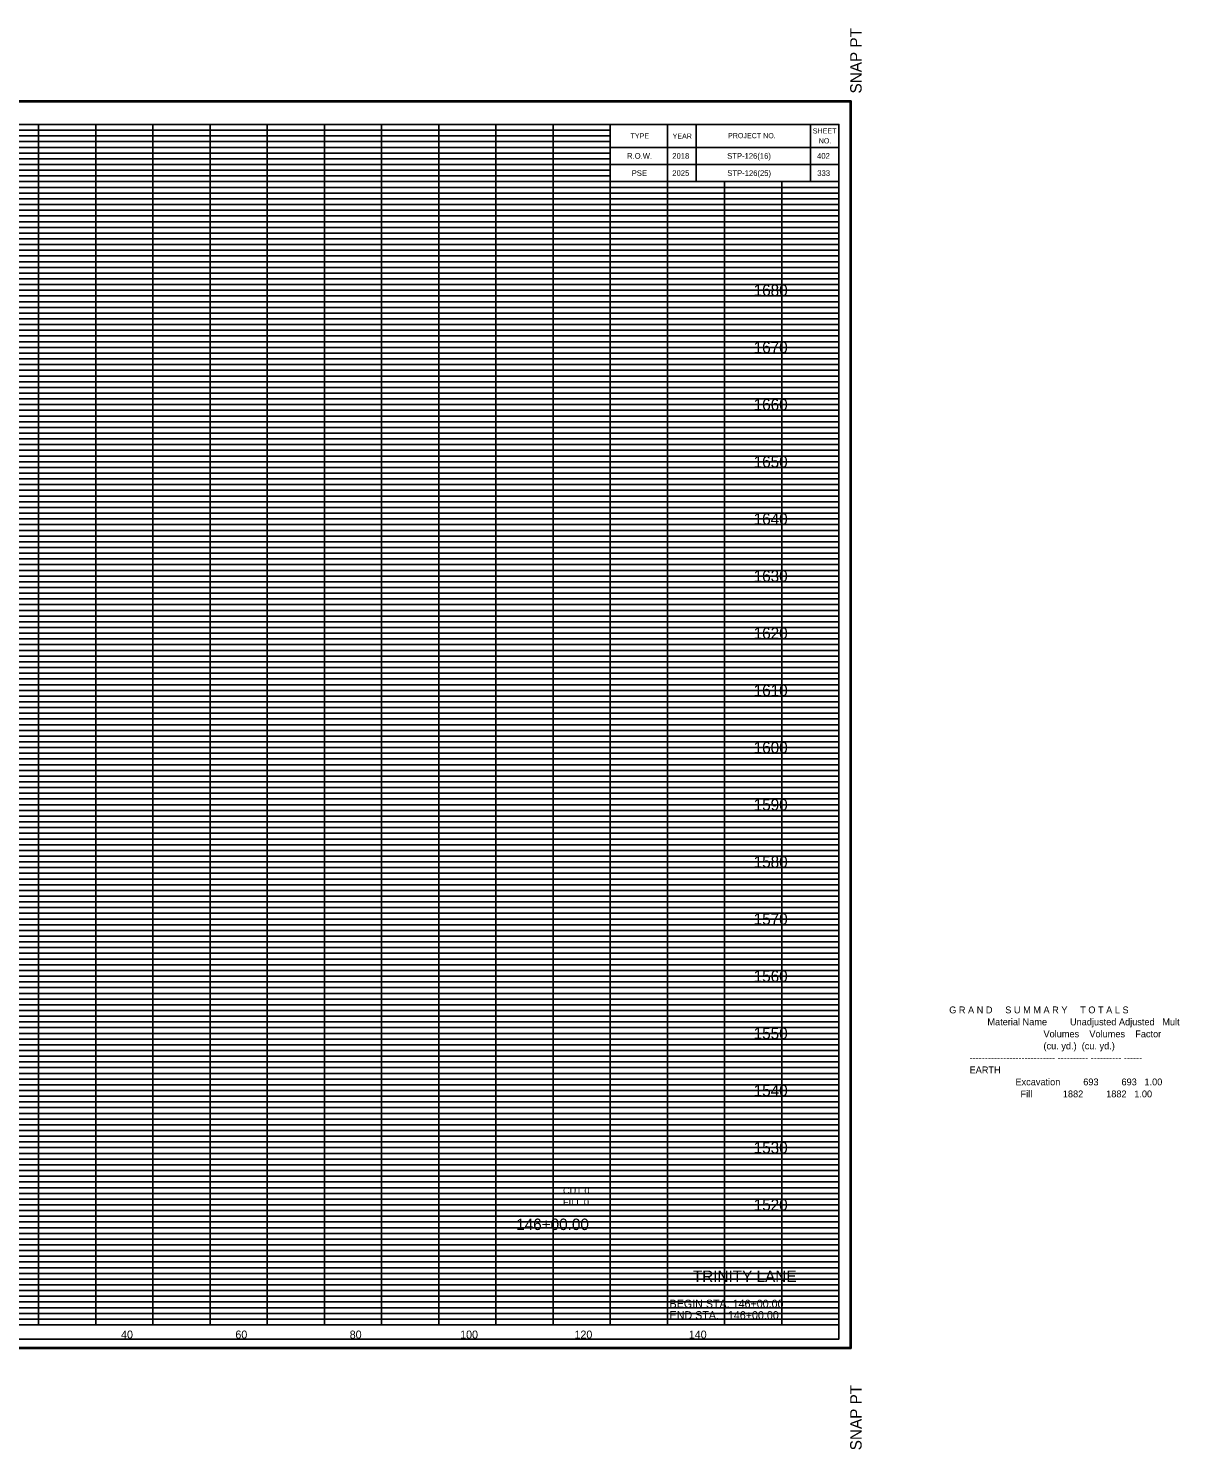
# Model space of a CAD drawing. Extents: x 980 to 1380, y 1248 to 3387.
# Drawn here: x 1178.2 to 1379.6, y 1248.2 to 1496.8 of the extents above; entities that cross this region are included whole.
import ezdxf

# ---------------------------------------------------------------- set-up
doc = ezdxf.new("R2010")
doc.units = 0
for name, color, linetype in [('DESIGN - SCRATCH - User 1', 7, 'Continuous'), ('DESIGN - SHEET - Corner Text', 7, 'Continuous'), ('DESIGN - SHEET - Light Grid', 7, 'Continuous'), ('DESIGN - SHEET - Linework', 7, 'Continuous'), ('DESIGN - SHEET - Plot Shape', 7, 'Continuous'), ('DESIGN - TYPICAL - Text', 7, 'Continuous')]:
    doc.layers.add(name, color=color, linetype=linetype)

# ---------------------------------------------------------------- blocks, each defined once
blk = doc.blocks.new('XSTSHT')
at = {"layer": 'DESIGN - SCRATCH - User 1'}
for p, q in [((28.5, 20.45), (28.5, 20.45)), ((29.24, 20.45), (29.24, 20.45)), ((30.49, 20.45), (30.49, 20.45)), ((31.74, 20.45), (31.74, 20.45)), ((28.5, 20.15), (28.5, 20.15)), ((29.24, 20.15), (29.24, 20.15)), ((30.49, 20.15), (30.49, 20.15)), ((31.74, 20.15), (31.74, 20.15))]:
    blk.add_line(p, q, dxfattribs=at)
at = {"layer": 'DESIGN - SHEET - Light Grid'}
for p, q in [((16, 20.9), (24, 20.9)), ((24, 20.9), (28, 20.9)), ((16, 20.8), (24, 20.8)), ((16, 20.7), (24, 20.7)), ((24, 20.8), (28, 20.8)), ((24, 20.7), (28, 20.7)), ((16, 20.6), (24, 20.6)), ((16, 20.5), (24, 20.5)), ((16, 20.4), (24, 20.4)), ((24, 20.6), (28, 20.6)), ((24, 20.5), (28, 20.5)), ((24, 20.4), (28, 20.4)), ((16, 20.3), (24, 20.3)), ((16, 20.2), (24, 20.2)), ((24, 20.3), (28, 20.3)), ((24, 20.2), (28, 20.2)), ((16, 20.1), (24, 20.1)), ((16, 19.9), (24, 19.9)), ((24, 20.1), (28, 20.1)), ((24, 19.9), (32, 19.9)), ((16, 19.8), (24, 19.8)), ((16, 19.7), (24, 19.7)), ((24, 19.8), (32, 19.8)), ((24, 19.7), (32, 19.7)), ((16, 19.6), (24, 19.6)), ((16, 19.5), (24, 19.5)), ((16, 19.4), (24, 19.4)), ((24, 19.6), (32, 19.6)), ((24, 19.5), (32, 19.5)), ((24, 19.4), (32, 19.4)), ((16, 19.3), (24, 19.3)), ((16, 19.2), (24, 19.2)), ((24, 19.3), (32, 19.3)), ((24, 19.2), (32, 19.2)), ((16, 19.1), (24, 19.1)), ((16, 18.9), (24, 18.9)), ((24, 19.1), (32, 19.1)), ((24, 18.9), (32, 18.9)), ((16, 18.8), (24, 18.8)), ((16, 18.7), (24, 18.7)), ((24, 18.8), (32, 18.8)), ((24, 18.7), (32, 18.7)), ((16, 18.6), (24, 18.6)), ((16, 18.5), (24, 18.5)), ((16, 18.4), (24, 18.4)), ((24, 18.6), (32, 18.6)), ((24, 18.5), (32, 18.5)), ((24, 18.4), (32, 18.4)), ((16, 18.3), (24, 18.3)), ((16, 18.2), (24, 18.2)), ((24, 18.3), (32, 18.3)), ((24, 18.2), (32, 18.2)), ((16, 18.1), (24, 18.1)), ((24, 18.1), (32, 18.1)), ((16, 17.9), (24, 17.9)), ((16, 17.8), (24, 17.8)), ((16, 17.7), (24, 17.7)), ((24, 17.9), (32, 17.9)), ((24, 17.8), (32, 17.8)), ((24, 17.7), (32, 17.7)), ((16, 17.6), (24, 17.6)), ((16, 17.5), (24, 17.5)), ((24, 17.6), (32, 17.6)), ((24, 17.5), (32, 17.5)), ((16, 17.4), (24, 17.4)), ((16, 17.3), (24, 17.3)), ((16, 17.2), (24, 17.2)), ((24, 17.4), (32, 17.4)), ((24, 17.3), (32, 17.3)), ((24, 17.2), (32, 17.2)), ((16, 17.1), (24, 17.1)), ((24, 17.1), (32, 17.1)), ((16, 16.9), (24, 16.9)), ((16, 16.8), (24, 16.8)), ((16, 16.7), (24, 16.7)), ((24, 16.9), (32, 16.9)), ((24, 16.8), (32, 16.8)), ((24, 16.7), (32, 16.7)), ((16, 16.6), (24, 16.6)), ((16, 16.5), (24, 16.5)), ((24, 16.6), (32, 16.6)), ((24, 16.5), (32, 16.5)), ((16, 16.4), (24, 16.4)), ((16, 16.3), (24, 16.3)), ((16, 16.2), (24, 16.2)), ((24, 16.4), (32, 16.4)), ((24, 16.3), (32, 16.3)), ((24, 16.2), (32, 16.2)), ((16, 16.1), (24, 16.1)), ((24, 16.1), (32, 16.1)), ((16, 15.9), (24, 15.9)), ((16, 15.8), (24, 15.8)), ((16, 15.7), (24, 15.7)), ((24, 15.9), (32, 15.9)), ((24, 15.8), (32, 15.8)), ((24, 15.7), (32, 15.7)), ((16, 15.6), (24, 15.6)), ((16, 15.5), (24, 15.5)), ((24, 15.6), (32, 15.6)), ((24, 15.5), (32, 15.5)), ((16, 15.4), (24, 15.4)), ((16, 15.3), (24, 15.3)), ((16, 15.2), (24, 15.2)), ((24, 15.4), (32, 15.4)), ((24, 15.3), (32, 15.3)), ((24, 15.2), (32, 15.2)), ((16, 15.1), (24, 15.1)), ((24, 15.1), (32, 15.1)), ((16, 14.9), (24, 14.9)), ((16, 14.8), (24, 14.8)), ((16, 14.7), (24, 14.7)), ((24, 14.9), (32, 14.9)), ((24, 14.8), (32, 14.8)), ((24, 14.7), (32, 14.7)), ((16, 14.6), (24, 14.6)), ((16, 14.5), (24, 14.5)), ((24, 14.6), (32, 14.6)), ((24, 14.5), (32, 14.5)), ((16, 14.4), (24, 14.4)), ((16, 14.3), (24, 14.3)), ((16, 14.2), (24, 14.2)), ((24, 14.4), (32, 14.4)), ((24, 14.3), (32, 14.3)), ((24, 14.2), (32, 14.2)), ((16, 14.1), (24, 14.1)), ((24, 14.1), (32, 14.1)), ((16, 13.9), (24, 13.9)), ((16, 13.8), (24, 13.8)), ((16, 13.7), (24, 13.7)), ((24, 13.9), (32, 13.9)), ((24, 13.8), (32, 13.8)), ((24, 13.7), (32, 13.7)), ((16, 13.6), (24, 13.6)), ((16, 13.5), (24, 13.5)), ((24, 13.6), (32, 13.6)), ((24, 13.5), (32, 13.5)), ((16, 13.4), (24, 13.4)), ((16, 13.3), (24, 13.3)), ((16, 13.2), (24, 13.2)), ((24, 13.4), (32, 13.4)), ((24, 13.3), (32, 13.3)), ((24, 13.2), (32, 13.2)), ((16, 13.1), (24, 13.1)), ((24, 13.1), (32, 13.1)), ((16, 12.9), (24, 12.9)), ((16, 12.8), (24, 12.8)), ((16, 12.7), (24, 12.7)), ((24, 12.9), (32, 12.9)), ((24, 12.8), (32, 12.8)), ((24, 12.7), (32, 12.7)), ((16, 12.6), (24, 12.6)), ((16, 12.5), (24, 12.5)), ((24, 12.6), (32, 12.6)), ((24, 12.5), (32, 12.5)), ((16, 12.4), (24, 12.4)), ((16, 12.3), (24, 12.3)), ((16, 12.2), (24, 12.2)), ((24, 12.4), (32, 12.4)), ((24, 12.3), (32, 12.3)), ((24, 12.2), (32, 12.2)), ((16, 12.1), (24, 12.1)), ((24, 12.1), (32, 12.1)), ((16, 11.9), (24, 11.9)), ((16, 11.8), (24, 11.8)), ((16, 11.7), (24, 11.7)), ((24, 11.9), (32, 11.9)), ((24, 11.8), (32, 11.8)), ((24, 11.7), (32, 11.7)), ((16, 11.6), (24, 11.6)), ((16, 11.5), (24, 11.5)), ((24, 11.6), (32, 11.6)), ((24, 11.5), (32, 11.5)), ((16, 11.4), (24, 11.4)), ((16, 11.3), (24, 11.3)), ((16, 11.2), (24, 11.2)), ((24, 11.4), (32, 11.4)), ((24, 11.3), (32, 11.3)), ((24, 11.2), (32, 11.2)), ((16, 11.1), (24, 11.1)), ((24, 11.1), (32, 11.1)), ((16, 10.9), (24, 10.9)), ((16, 10.8), (24, 10.8)), ((16, 10.7), (24, 10.7)), ((24, 10.9), (32, 10.9)), ((24, 10.8), (32, 10.8)), ((24, 10.7), (32, 10.7)), ((16, 10.6), (24, 10.6)), ((16, 10.5), (24, 10.5)), ((24, 10.6), (32, 10.6)), ((24, 10.5), (32, 10.5)), ((16, 10.4), (24, 10.4)), ((16, 10.3), (24, 10.3)), ((16, 10.2), (24, 10.2)), ((24, 10.4), (32, 10.4)), ((24, 10.3), (32, 10.3)), ((24, 10.2), (32, 10.2)), ((16, 10.1), (24, 10.1)), ((24, 10.1), (32, 10.1)), ((16, 9.9), (24, 9.9)), ((16, 9.8), (24, 9.8)), ((16, 9.7), (24, 9.7)), ((24, 9.9), (32, 9.9)), ((24, 9.8), (32, 9.8)), ((24, 9.7), (32, 9.7)), ((16, 9.6), (24, 9.6)), ((16, 9.5), (24, 9.5)), ((24, 9.6), (32, 9.6)), ((24, 9.5), (32, 9.5)), ((16, 9.4), (24, 9.4)), ((16, 9.3), (24, 9.3)), ((16, 9.2), (24, 9.2)), ((24, 9.4), (32, 9.4)), ((24, 9.3), (32, 9.3)), ((24, 9.2), (32, 9.2)), ((16, 9.1), (24, 9.1)), ((24, 9.1), (32, 9.1)), ((16, 8.9), (24, 8.9)), ((16, 8.8), (24, 8.8)), ((24, 8.9), (32, 8.9)), ((24, 8.8), (32, 8.8)), ((16, 8.7), (24, 8.7)), ((16, 8.6), (24, 8.6)), ((16, 8.5), (24, 8.5)), ((24, 8.7), (32, 8.7)), ((24, 8.6), (32, 8.6)), ((24, 8.5), (32, 8.5)), ((16, 8.4), (24, 8.4)), ((16, 8.3), (24, 8.3)), ((24, 8.4), (32, 8.4)), ((24, 8.3), (32, 8.3)), ((16, 8.2), (24, 8.2)), ((16, 8.1), (24, 8.1)), ((24, 8.2), (32, 8.2)), ((24, 8.1), (32, 8.1)), ((16, 7.9), (24, 7.9)), ((16, 7.8), (24, 7.8)), ((24, 7.9), (32, 7.9)), ((24, 7.8), (32, 7.8)), ((16, 7.7), (24, 7.7)), ((16, 7.6), (24, 7.6)), ((16, 7.5), (24, 7.5)), ((24, 7.7), (32, 7.7)), ((24, 7.6), (32, 7.6)), ((24, 7.5), (32, 7.5)), ((16, 7.4), (24, 7.4)), ((16, 7.3), (24, 7.3)), ((24, 7.4), (32, 7.4)), ((24, 7.3), (32, 7.3)), ((16, 7.2), (24, 7.2)), ((16, 7.1), (24, 7.1)), ((24, 7.2), (32, 7.2)), ((24, 7.1), (32, 7.1)), ((16, 6.9), (24, 6.9)), ((16, 6.8), (24, 6.8)), ((24, 6.9), (32, 6.9)), ((24, 6.8), (32, 6.8)), ((16, 6.7), (24, 6.7)), ((16, 6.6), (24, 6.6)), ((16, 6.5), (24, 6.5)), ((24, 6.7), (32, 6.7)), ((24, 6.6), (32, 6.6)), ((24, 6.5), (32, 6.5)), ((16, 6.4), (24, 6.4)), ((16, 6.3), (24, 6.3)), ((24, 6.4), (32, 6.4)), ((24, 6.3), (32, 6.3)), ((16, 6.2), (24, 6.2)), ((16, 6.1), (24, 6.1)), ((24, 6.2), (32, 6.2)), ((24, 6.1), (32, 6.1)), ((16, 5.9), (24, 5.9)), ((16, 5.8), (24, 5.8)), ((24, 5.9), (32, 5.9)), ((24, 5.8), (32, 5.8)), ((16, 5.7), (24, 5.7)), ((16, 5.6), (24, 5.6)), ((16, 5.5), (24, 5.5)), ((24, 5.7), (32, 5.7)), ((24, 5.6), (32, 5.6)), ((24, 5.5), (32, 5.5)), ((16, 5.4), (24, 5.4)), ((16, 5.3), (24, 5.3)), ((24, 5.4), (32, 5.4)), ((24, 5.3), (32, 5.3)), ((16, 5.2), (24, 5.2)), ((16, 5.1), (24, 5.1)), ((24, 5.2), (32, 5.2)), ((24, 5.1), (32, 5.1)), ((16, 4.9), (24, 4.9)), ((16, 4.8), (24, 4.8)), ((24, 4.9), (32, 4.9)), ((24, 4.8), (32, 4.8)), ((16, 4.7), (24, 4.7)), ((16, 4.6), (24, 4.6)), ((16, 4.5), (24, 4.5)), ((24, 4.7), (32, 4.7)), ((24, 4.6), (32, 4.6)), ((24, 4.5), (32, 4.5)), ((16, 4.4), (24, 4.4)), ((16, 4.3), (24, 4.3)), ((24, 4.4), (32, 4.4)), ((24, 4.3), (32, 4.3)), ((16, 4.2), (24, 4.2)), ((16, 4.1), (24, 4.1)), ((24, 4.2), (32, 4.2)), ((24, 4.1), (32, 4.1)), ((16, 3.9), (24, 3.9)), ((16, 3.8), (24, 3.8)), ((24, 3.9), (32, 3.9)), ((24, 3.8), (32, 3.8)), ((16, 3.7), (24, 3.7)), ((16, 3.6), (24, 3.6)), ((16, 3.5), (24, 3.5)), ((24, 3.7), (32, 3.7)), ((24, 3.6), (32, 3.6)), ((24, 3.5), (32, 3.5)), ((16, 3.4), (24, 3.4)), ((16, 3.3), (24, 3.3)), ((24, 3.4), (32, 3.4)), ((24, 3.3), (32, 3.3)), ((16, 3.2), (24, 3.2)), ((16, 3.1), (24, 3.1)), ((24, 3.2), (32, 3.2)), ((24, 3.1), (32, 3.1)), ((16, 2.9), (24, 2.9)), ((16, 2.8), (24, 2.8)), ((24, 2.9), (32, 2.9)), ((24, 2.8), (32, 2.8)), ((16, 2.7), (24, 2.7)), ((16, 2.6), (24, 2.6)), ((16, 2.5), (24, 2.5)), ((24, 2.7), (32, 2.7)), ((24, 2.6), (32, 2.6)), ((24, 2.5), (32, 2.5)), ((16, 2.4), (24, 2.4)), ((16, 2.3), (24, 2.3)), ((24, 2.4), (32, 2.4)), ((24, 2.3), (32, 2.3)), ((16, 2.2), (24, 2.2)), ((16, 2.1), (24, 2.1)), ((24, 2.2), (32, 2.2)), ((24, 2.1), (32, 2.1)), ((16, 1.9), (24, 1.9)), ((16, 1.8), (24, 1.8)), ((24, 1.9), (32, 1.9)), ((24, 1.8), (32, 1.8)), ((16, 1.7), (24, 1.7)), ((16, 1.6), (24, 1.6)), ((16, 1.5), (24, 1.5)), ((24, 1.7), (32, 1.7)), ((24, 1.6), (32, 1.6)), ((24, 1.5), (32, 1.5)), ((16, 1.4), (24, 1.4)), ((16, 1.3), (24, 1.3)), ((24, 1.4), (32, 1.4)), ((24, 1.3), (32, 1.3)), ((16, 1.2), (24, 1.2)), ((16, 1.1), (24, 1.1)), ((24, 1.2), (32, 1.2)), ((24, 1.1), (32, 1.1)), ((16, 0.9), (24, 0.9)), ((16, 0.8), (24, 0.8)), ((24, 0.9), (32, 0.9)), ((24, 0.8), (32, 0.8)), ((16, 0.7), (24, 0.7)), ((16, 0.6), (24, 0.6)), ((16, 0.5), (24, 0.5)), ((24, 0.7), (32, 0.7)), ((24, 0.6), (32, 0.6)), ((24, 0.5), (32, 0.5)), ((16, 0.4), (24, 0.4)), ((16, 0.3), (24, 0.3)), ((24, 0.4), (32, 0.4)), ((24, 0.3), (32, 0.3)), ((16, 0.2), (24, 0.2)), ((16, 0.1), (24, 0.1)), ((24, 0.2), (32, 0.2)), ((24, 0.1), (32, 0.1))]:
    blk.add_line(p, q, dxfattribs=at)
at = {"layer": 'DESIGN - SHEET - Linework'}
for p, q in [((-1.823, 21.414), (32.217, 21.414)), ((32.217, 21.414), (32.217, -0.414)), ((18, 0), (18, 21)), ((19, 0), (19, 21)), ((20, 0), (20, 21)), ((21, 0), (21, 21)), ((22, 0), (22, 21)), ((23, 0), (23, 21)), ((24, 0), (24, 21)), ((25, 0), (25, 21)), ((26, 0), (26, 21)), ((27, 0), (27, 21)), ((0, 20), (28, 20)), ((28, 0), (28, 20)), ((29, 0), (29, 20)), ((30, 0), (30, 20)), ((31, 0), (31, 20)), ((0, 19), (32, 19)), ((0, 18), (32, 18)), ((0, 17), (32, 17)), ((0, 16), (32, 16)), ((0, 15), (32, 15)), ((0, 14), (32, 14)), ((0, 13), (32, 13)), ((0, 12), (32, 12)), ((0, 11), (32, 11)), ((0, 10), (32, 10)), ((0, 9), (32, 9)), ((0, 8), (32, 8)), ((0, 7), (32, 7)), ((0, 6), (32, 6)), ((0, 5), (32, 5)), ((0, 4), (32, 4)), ((0, 3), (32, 3)), ((0, 2), (32, 2)), ((0, 1), (32, 1)), ((-1.823, -0.414), (32.217, -0.414))]:
    blk.add_line(p, q, dxfattribs=at)
for points in [[(0, 21), (0, 0), (32, 0), (32, 21), (0, 21)], [(28, 21), (28, 20), (32, 20), (32, 21), (31.5, 21), (31.5, 20), (29.5, 20), (29.5, 21), (29, 21), (29, 20), (32, 20), (28, 20), (28, 20.3), (32, 20.3), (32, 20.6), (28, 20.6)]]:
    blk.add_lwpolyline(points, dxfattribs=at)
at = {"layer": 'DESIGN - SHEET - Plot Shape'}
for points in [[(-1.803, 21.394), (32.197, 21.394), (32.197, -0.394), (-1.803, -0.394)], [(-0.85, 21), (32, 21), (32, -0.25), (-0.85, -0.25)]]:
    blk.add_lwpolyline(points, close=True, dxfattribs=at)
at = {"layer": 'DESIGN - SHEET - Corner Text'}
for s, p in [('  SNAP PT', (32.397, 21.394)), ('SNAP PT  ', (32.397, -2.194))]:
    blk.add_text(s, height=0.2, rotation=90, dxfattribs=at).set_placement(p)
for s, p in [('SHEET', (31.543, 20.843)), ('TYPE', (28.354, 20.756)), ('YEAR', (29.09, 20.752)), ('PROJECT NO.', (30.06, 20.76)), ('NO.', (31.646, 20.669))]:
    blk.add_text(s, height=0.09, dxfattribs=at).set_placement(p)

msp = doc.modelspace()

# ---------------------------------------------------------------- linework, layer by layer
at = {"layer": 'DESIGN - SHEET - Plot Shape'}
msp.add_lwpolyline([(991.5, 1267.5), (1320, 1267.5), (1320, 1480), (991.5, 1480)], close=True, dxfattribs=at)

# ---------------------------------------------------------------- block references
at = {"layer": 'DESIGN - TYPICAL - Text', "xscale": 10, "yscale": 10}
msp.add_blockref('XSTSHT', (1000, 1270), dxfattribs=at)

# ---------------------------------------------------------------- texts
at = {"layer": 'DESIGN - SHEET - Corner Text'}
for s, height, p in [('R.O.W.', 1, (1282.94, 1474)), ('2018', 1, (1290.85, 1474)), ('STP-126(16)', 1, (1300.45, 1474)), ('402', 1, (1316.18, 1474)), ('PSE', 1, (1283.75, 1471)), ('2025', 1, (1290.85, 1471)), ('STP-126(25)', 1, (1300.47, 1471)), ('333', 1, (1316.22, 1471)), ('TRINITY LANE', 2, (1294.45, 1277.5)), ('BEGIN STA. 146+00.00', 1.4, (1290.38, 1273)), ('END STA.   146+00.00', 1.4, (1290.38, 1271))]:
    msp.add_text(s, height=height, dxfattribs=at).set_placement(p)
at = {"layer": 'DESIGN - TYPICAL - Text'}
for s, height, p in [('     1680     ', 2, (1301.37, 1450)), ('     1670     ', 2, (1301.37, 1440)), ('     1660     ', 2, (1301.37, 1430)), ('     1650     ', 2, (1301.37, 1420)), ('     1640     ', 2, (1301.37, 1410)), ('     1630     ', 2, (1301.37, 1400)), ('     1620     ', 2, (1301.37, 1390)), ('     1610     ', 2, (1301.37, 1380)), ('     1600     ', 2, (1301.37, 1370)), ('     1590     ', 2, (1301.37, 1360)), ('     1580     ', 2, (1301.37, 1350)), ('     1570     ', 2, (1301.37, 1340)), ('     1560     ', 2, (1301.37, 1330)), ('G R A N D     S U M M A R Y     T O T A L S', 1.2, (1339.29, 1324.5)), ('               Material Name         Unadjusted Adjusted   Mult', 1.2, (1339.29, 1322.4)), ('     1550     ', 2, (1301.37, 1320)), ('                                     Volumes    Volumes    Factor', 1.2, (1339.29, 1320.3)), ('                                     (cu. yd.)  (cu. yd.)', 1.2, (1339.29, 1318.2)), ('        ---------------------------- ---------- ---------- ------', 1.2, (1339.29, 1316.1)), ('        EARTH', 1.2, (1339.29, 1314)), ('                          Excavation         693         693   1.00', 1.2, (1339.29, 1311.9)), ('     1540     ', 2, (1301.37, 1310)), ('                            Fill            1882         1882   1.00', 1.2, (1339.29, 1309.8)), ('     1530     ', 2, (1301.37, 1300)), ('CUT 0', 1.2, (1271.73, 1292.88)), ('FILL 0', 1.2, (1271.73, 1290.88)), ('     1520     ', 2, (1301.37, 1290)), ('     146+00.00     ', 2, (1259.83, 1286.59)), ('     40     ', 1.4, (1191.82, 1267.6)), ('     60     ', 1.4, (1211.82, 1267.6)), ('     80     ', 1.4, (1231.82, 1267.6)), ('     100     ', 1.4, (1251.14, 1267.6)), ('     120     ', 1.4, (1271.14, 1267.6)), ('     140     ', 1.4, (1291.14, 1267.6))]:
    msp.add_text(s, height=height, dxfattribs=at).set_placement(p)

doc.saveas('drawing.dxf')
